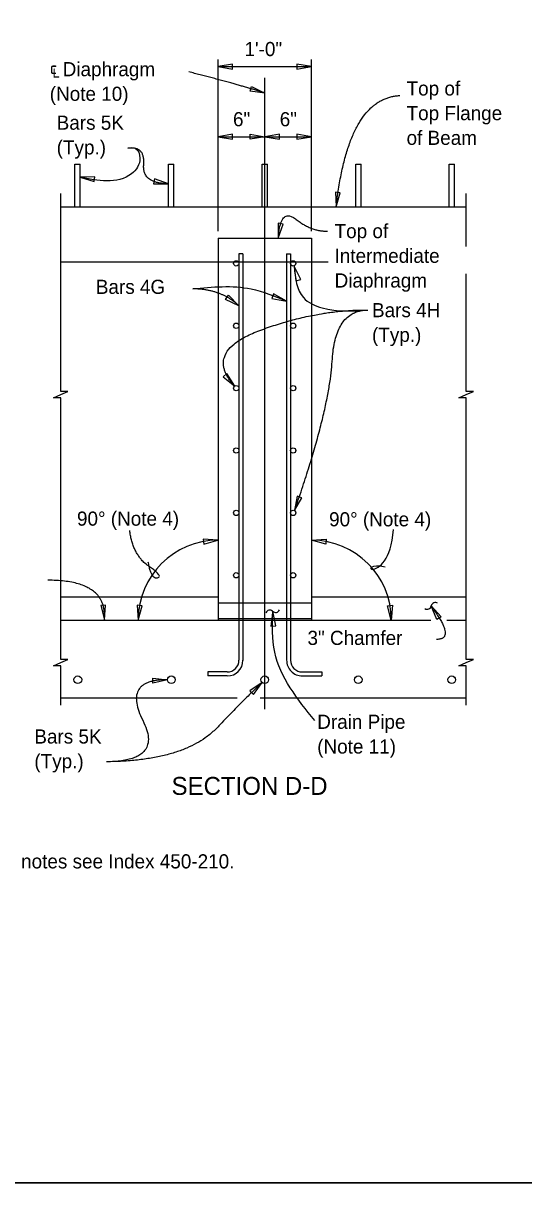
# Model space of a CAD drawing. Extents: x 0 to 30.8, y 0 to 19.8.
# Drawn here: x 10.58 to 15.94, y 0 to 12.4 of the extents above; entities that cross this region are included whole.
import ezdxf

# ---------------------------------------------------------------- set-up
doc = ezdxf.new("R2010")
doc.units = 0
for name, color, linetype in [('ActivePts-ConstElements', 7, 'Continuous'), ('BeamConc', 7, 'Continuous'), ('BeamConc_h', 7, 'Continuous'), ('CL_Major', 7, 'Continuous'), ('Dimension', 7, 'Continuous'), ('Miscellaneous', 7, 'Continuous'), ('Miscellaneous1', 7, 'Continuous'), ('Rebar', 7, 'Continuous'), ('TextStructures', 7, 'Continuous')]:
    doc.layers.add(name, color=color, linetype=linetype)

msp = doc.modelspace()

# ---------------------------------------------------------------- linework, layer by layer
at = {"layer": 'ActivePts-ConstElements'}
msp.add_lwpolyline([(0, 0), (30.765, 0), (30.765, 19.441), (0, 19.441)], close=True, dxfattribs=at)
at = {"layer": 'BeamConc'}
for p, q in [((10.982, 10.433), (15.319, 10.433)), ((12.665, 10.1), (12.665, 6.016)), ((12.665, 10.1), (13.665, 10.1)), ((13.665, 10.1), (13.665, 6.016)), ((10.982, 6.266), (12.665, 6.266)), ((13.665, 6.266), (15.319, 6.266)), ((10.982, 6.016), (14.941, 6.016)), ((15.111, 6.016), (15.319, 6.016)), ((10.982, 5.183), (12.869, 5.183)), ((13.116, 5.183), (15.319, 5.183))]:
    msp.add_line(p, q, dxfattribs=at)
at = {"layer": 'BeamConc_h'}
msp.add_line((10.982, 9.845), (13.844, 9.845), dxfattribs=at)
at = {"layer": 'CL_Major'}
msp.add_line((13.165, 5.065), (13.165, 11.812), dxfattribs=at)
at = {"layer": 'Dimension'}
for p, q in [((12.665, 10.175), (12.665, 12.009)), ((12.665, 11.933), (13.665, 11.933)), ((13.665, 10.175), (13.665, 12.009)), ((12.665, 11.183), (13.665, 11.183))]:
    msp.add_line(p, q, dxfattribs=at)
for points in [[(12.665, 11.933), (12.821, 11.907), (12.821, 11.96)], [(13.665, 11.933), (13.508, 11.96), (13.508, 11.907)], [(13.165, 11.65), (13.008, 11.669), (13.022, 11.719)], [(12.665, 11.183), (12.821, 11.157), (12.821, 11.21)], [(13.165, 11.183), (13.008, 11.157), (13.008, 11.21)], [(13.165, 11.183), (13.321, 11.157), (13.321, 11.21)], [(13.665, 11.183), (13.508, 11.21), (13.508, 11.157)], [(11.189, 10.752), (11.34, 10.703), (11.348, 10.756)], [(11.189, 10.752), (11.19, 10.752), (11.19, 10.752)], [(12.134, 10.68), (11.984, 10.733), (11.975, 10.681)], [(13.929, 10.433), (13.973, 10.585), (13.921, 10.591)], [(13.31, 10.1), (13.361, 10.25), (13.308, 10.258)], [(13.48, 9.798), (13.499, 9.641), (13.55, 9.656)], [(12.889, 9.377), (12.746, 9.444), (12.776, 9.488)], [(13.399, 9.427), (13.259, 9.503), (13.242, 9.453)], [(12.843, 8.517), (12.758, 8.651), (12.719, 8.615)], [(13.484, 7.186), (13.56, 7.324), (13.51, 7.342)], [(12.664, 6.87), (12.507, 6.882), (12.512, 6.829)], [(13.665, 6.87), (13.822, 6.882), (13.817, 6.829)], [(11.449, 6.017), (11.463, 6.174), (11.41, 6.17)], [(11.811, 6.016), (11.852, 6.169), (11.799, 6.174)], [(13.25, 6.11), (13.231, 5.952), (13.284, 5.955)], [(14.518, 6.016), (14.477, 6.169), (14.53, 6.174)], [(14.945, 6.167), (15.051, 6.049), (15.006, 6.021)], [(12.123, 5.378), (11.969, 5.341), (11.966, 5.394)], [(13.138, 5.347), (13.006, 5.259), (13.043, 5.22)]]:
    msp.add_lwpolyline(points, close=True, dxfattribs=at)
for points in [[(10.982, 6.016), (10.982, 8.392), (10.905, 8.392), (10.982, 8.426), (11.06, 8.459), (10.982, 8.459), (10.982, 10.575)], [(15.319, 10.009), (15.319, 10.575)], [(15.319, 6.016), (15.319, 8.392), (15.242, 8.392), (15.319, 8.426), (15.397, 8.459), (15.319, 8.459), (15.319, 9.716)], [(10.982, 5.107), (10.982, 5.527), (10.905, 5.527), (10.982, 5.561), (11.06, 5.595), (10.982, 5.595), (10.982, 6.016)], [(15.319, 5.107), (15.319, 5.527), (15.242, 5.527), (15.319, 5.561), (15.397, 5.595), (15.319, 5.595), (15.319, 6.016)]]:
    msp.add_lwpolyline(points, dxfattribs=at)
for centre, radius, start, end in [((12.665, 6.016), 0.854, 90, 180), ((13.665, 6.016), 0.854, 0, 90), ((14.989, 6.158), 0.0447, 56.5869, 168.3141), ((13.219, 6.077), 0.0447, 46.9499, 158.6771), ((13.28, 6.142), 0.0447, 226.9499, 338.6771), ((14.902, 6.176), 0.0447, 236.5869, 348.3141)]:
    msp.add_arc(centre, radius, start, end, dxfattribs=at)
for points, degree in [([(13.165, 11.651), (12.798, 11.765), (12.353, 11.876)], 2), ([(13.929, 10.433), (14.059, 11.597), (14.608, 11.623)], 2), ([(12.134, 10.68), (11.853, 10.684), (11.887, 11.085), (11.699, 11.06)], 2), ([(13.31, 10.1), (13.33, 10.433), (13.671, 10.166), (13.837, 10.175)], 2), ([(12.889, 9.377), (12.692, 9.556), (12.395, 9.557)], 2), ([(12.843, 8.517), (12.506, 8.888), (13.723, 9.338), (14.268, 9.33)], 2), ([(13.484, 7.186), (13.857, 8.254), (13.916, 9.329), (14.268, 9.33)], 2), ([(11.915, 6.64), (11.946, 6.453), (12.087, 6.481), (11.756, 6.706), (11.72, 6.974)], 2), ([(14.453, 6.58), (14.297, 6.623), (14.242, 6.481), (14.519, 6.653), (14.542, 6.983)], 3), ([(11.448, 6.016), (11.489, 6.442), (10.843, 6.442)], 2), ([(14.97, 6.128), (15.205, 5.809), (15.001, 5.809)], 2), ([(12.123, 5.378), (11.639, 5.381), (12.082, 4.505), (11.472, 4.501)], 2), ([(13.138, 5.347), (12.99, 5.217), (12.315, 4.51), (11.472, 4.501)], 2)]:
    msp.add_open_spline(points, degree=degree, dxfattribs=at)
for points in [[(11.699, 11.06), (11.78, 11.06), (11.83, 10.954), (11.741, 10.787), (11.477, 10.71), (11.189, 10.752)], [(13.48, 9.798), (13.578, 9.463), (13.78, 9.354), (14.268, 9.33)], [(12.395, 9.557), (13.018, 9.557), (13.399, 9.427)], [(13.7, 4.941), (13.271, 5.673), (13.25, 6.11)]]:
    msp.add_spline(points, degree=3, dxfattribs=at)
at = {"layer": 'Miscellaneous'}
for p, q in [((12.678, 6.2), (13.665, 6.2)), ((12.678, 6.032), (13.665, 6.032))]:
    msp.add_line(p, q, dxfattribs=at)
at = {"layer": 'Miscellaneous1'}
msp.add_lwpolyline([(0, 19.8), (30.8, 19.8), (30.8, 0), (0, 0)], close=True, dxfattribs=at)
at = {"layer": 'Rebar'}
for p, q in [((11.133, 10.433), (11.133, 10.891)), ((11.133, 10.891), (11.191, 10.891)), ((11.191, 10.433), (11.191, 10.891)), ((12.134, 10.433), (12.134, 10.891)), ((12.134, 10.891), (12.191, 10.891)), ((12.191, 10.433), (12.191, 10.891)), ((13.136, 10.433), (13.136, 10.891)), ((13.136, 10.891), (13.193, 10.891)), ((13.193, 10.433), (13.193, 10.891)), ((14.139, 10.433), (14.139, 10.891)), ((14.139, 10.891), (14.196, 10.891)), ((14.196, 10.433), (14.196, 10.891)), ((15.139, 10.433), (15.139, 10.891)), ((15.139, 10.891), (15.196, 10.891)), ((15.196, 10.433), (15.196, 10.891)), ((12.889, 9.933), (12.889, 5.586)), ((12.93, 9.933), (12.889, 9.933)), ((12.93, 9.933), (12.93, 5.584)), ((13.399, 9.933), (13.399, 5.584)), ((13.399, 9.933), (13.441, 9.933)), ((13.441, 9.933), (13.441, 5.586)), ((12.555, 5.461), (12.555, 5.42)), ((12.764, 5.461), (12.555, 5.461)), ((13.566, 5.461), (13.774, 5.461)), ((13.774, 5.461), (13.774, 5.42)), ((12.764, 5.42), (12.555, 5.42)), ((13.566, 5.42), (13.774, 5.42))]:
    msp.add_line(p, q, dxfattribs=at)
for centre, radius in [((12.86, 9.829), 0.0287), ((13.469, 9.829), 0.0287), ((12.86, 9.162), 0.0287), ((13.469, 9.162), 0.0287), ((12.86, 8.495), 0.0287), ((13.469, 8.495), 0.0287), ((12.86, 7.829), 0.0287), ((13.469, 7.829), 0.0287), ((12.86, 7.162), 0.0287), ((13.469, 7.162), 0.0287), ((12.86, 6.495), 0.0287), ((13.469, 6.495), 0.0287), ((11.165, 5.378), 0.0413), ((12.165, 5.378), 0.0413), ((13.165, 5.378), 0.0413), ((14.165, 5.378), 0.0413), ((15.165, 5.378), 0.0413)]:
    msp.add_circle(centre, radius, dxfattribs=at)
for centre, radius, start, end in [((12.764, 5.586), 0.125, 270, 0), ((12.764, 5.586), 0.167, 270, 360), ((13.566, 5.586), 0.167, 179.24, 270), ((13.566, 5.586), 0.125, 180, 270)]:
    msp.add_arc(centre, radius, start, end, dxfattribs=at)

# ---------------------------------------------------------------- texts
at = {"layer": 'Dimension'}
for s, p in [('Top of', (14.682, 11.624)), ('Bars 5K', (10.939, 11.258)), ('Top Flange', (14.682, 11.36)), ('of Beam', (14.682, 11.096)), ('(Typ.)', (10.939, 10.994)), ('Top of', (13.912, 10.099)), ('Intermediate', (13.912, 9.835)), ('Diaphragm', (13.912, 9.571)), ('Bars 4H', (14.312, 9.254)), ('(Typ.)', (14.312, 8.99)), ('Drain Pipe', (13.726, 4.853)), ('Bars 5K', (10.7, 4.696)), ('(Note 11)', (13.726, 4.589)), ('(Typ.)', (10.7, 4.432))]:
    msp.add_text(s, height=0.1512, dxfattribs=at).set_placement(p)
at = {"layer": 'TextStructures'}
for s, height, p in [('1\'-0"', 0.1512, (12.948, 12.045)), ('℄ Diaphragm', 0.1512, (10.865, 11.83)), ('(Note 10)', 0.1512, (10.865, 11.567)), ('6"', 0.1512, (12.825, 11.295)), ('6"', 0.1512, (13.325, 11.295)), ('Bars 4G', 0.1512, (11.358, 9.503)), ('90° (Note 4)', 0.1512, (11.156, 7.025)), ('90° (Note 4)', 0.1512, (13.853, 7.018)), ('3" Chamfer', 0.1512, (13.622, 5.75)), ('SECTION D-D', 0.192, (12.168, 4.147)), ('For referenced notes see Index 450-210.', 0.1512, (9.176, 3.361))]:
    msp.add_text(s, height=height, dxfattribs=at).set_placement(p)

doc.saveas('drawing.dxf')
